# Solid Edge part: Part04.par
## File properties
Author: Robert a Rhodes jr
Template: Normal.par
Last saved by: CADCIM
Revision: 4
Application: Solid Edge
Accuracy: 0.99
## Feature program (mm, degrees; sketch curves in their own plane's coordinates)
body "unnamed Body 1"
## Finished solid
Body 1: solid body, 43 faces, 102 edges, 68 vertices.
  Faces by surface: cylinder 28, plane 15
  Edges by curve: circle 56, line 46
Bounding box of the edges (mm): 1353.852 x 457.200 x 1295.400, from (-676.9261, -203.2, -533.4) to (676.9261, 254, 762).
Cylindrical faces by radius (mm): R50.8 x6, R95.25 x6, R127 x5, R152.4 x2, R254 x2, R431.8 x2, R508 x2, R533.4 x3
Planar faces by outward normal: +x 1, +y 7, -x 1, -y 2, oblique 4
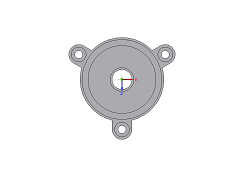
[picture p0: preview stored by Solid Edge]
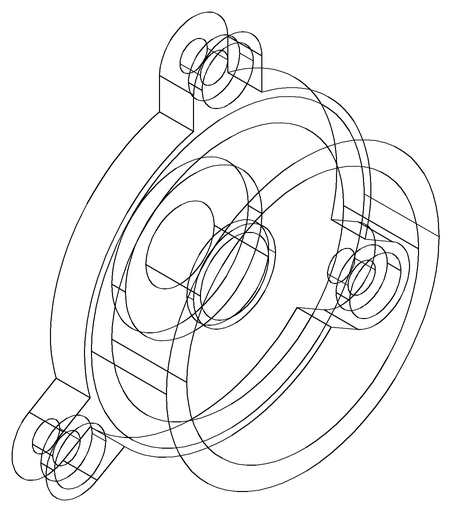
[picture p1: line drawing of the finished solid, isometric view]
